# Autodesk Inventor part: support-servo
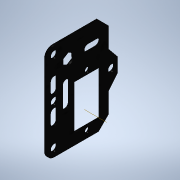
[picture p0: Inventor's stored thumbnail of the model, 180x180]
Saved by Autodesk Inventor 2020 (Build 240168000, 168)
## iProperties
Created: 2021-10
Part Number: support-servo
Material: Aluminium 6061
Document SubType Name: Tôle
Designer: bruno
Density: 4.82565 g/cm^3
Sheet Metal Rule: Par défaut_mm
Appearance: Noir
Mass: 5 g
Surface Area: 24.6113 cm^2
Volume: 1.03613 cm^3
Author: bruno
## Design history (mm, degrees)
sketch "Esquisse1"
  geometry: L1 (4, 0)-(44, 0); L2 (48, -4)-(48, -26); L3 (0, -26)-(0, -4); L4 (24, 0)-(24, -30.702); L5 (33.07, -2.25)-(28.57, -2.25); L6 (28.57, -5.75)-(33.07, -5.75); L7 (14.93, -2.25)-(19.43, -2.25); L8 (19.43, -5.75)-(14.93, -5.75); L9 (27.3, -26.952)-(5.3, -26.952); L10 (5.3, -26.952)-(5.3, -13.952); L11 (5.3, -13.952)-(27.3, -13.952); L12 (27.3, -13.952)-(27.3, -26.952); L13 (5, -30.982)-(0, -26); L14 (43, -30.982)-(48, -26); L15 (1.955, -20.452)-(29.582, -20.452); L16 (27.3, -26.952)-(43, -26.952); L17 (40.295, -20.701)-(40.3, -25.201); L18 (36.8, -20.832)-(36.8, -25.202); L19 (36.8, -26.952)-(36.8, -29.253); L20 (23.989, -34.202)-(23.989, -35.452); L21 (23.989, -35.452)-(27.489, -35.452); L22 (27.489, -35.452)-(32.95, -30.982); L23 (20.489, -35.452)-(15.027, -30.982); L24 (23.989, -35.452)-(20.489, -35.452); L25 (38.55, -25.202)-(38.55, -1.172); L26 (37.014, -8.556)-(39.898, -8.448); L27 (39.898, -8.448)-(41.435, -10.892); L28 (41.435, -10.892)-(40.086, -13.444); L29 (40.086, -13.444)-(37.202, -13.552); L30 (37.202, -13.552)-(35.665, -11.108); L31 (35.665, -11.108)-(37.014, -8.556); L32 (43, -30.982)-(32.95, -30.982); L33 (15.027, -30.982)-(5, -30.982); L34 (28.75, -11.75)-(24, -11.75); L35 (28.75, -8.25)-(24, -8.25); L36 (19.25, -8.25)-(24, -8.25); L37 (19.25, -11.75)-(24, -11.75); C1 r 1.75 at (44, -4); C2 r 1.75 at (4, -4); C3 r 1.75 at (24, -4); C4 r 1.25 at (29.3, -20.452); C5 r 1.25 at (3.3, -20.452); A1 r 4 centre (44, -4) between (48, -4) and (44, 0); A2 r 4 centre (4, -4) between (4, 0) and (0, -4); A3 r 1.75 centre (33.07, -4) between (33.07, -5.75) and (33.07, -2.25); A4 r 1.75 centre (28.57, -4) between (28.57, -2.25) and (28.57, -5.75); A5 r 1.75 centre (14.93, -4) between (14.93, -2.25) and (14.93, -5.75); A6 r 1.75 centre (19.43, -4) between (19.43, -5.75) and (19.43, -2.25); A7 r 1.75 centre (38.55, -25.202) between (36.8, -25.202) and (40.3, -25.201); A8 r 1.75 centre (38.545, -20.702) between (40.295, -20.701) and (36.8, -20.832); A9 r 1.75 centre (24.005, -32.452) between (23.989, -34.202) and (24, -30.702); A10 r 1.75 centre (28.75, -10) between (28.75, -11.75) and (28.75, -8.25); A11 r 1.75 centre (19.25, -10) between (19.25, -8.25) and (19.25, -11.75); 5 further points
  constraints: 74 end point, 22 point on circle, 16 centre point, 13 point on line, 11 symmetric about line, 11 tangent, 6 parallel, 5 perpendicular, 4 horizontal, 4 vertical, 2 coincident, 1 equal length, 1 equal radius, 1 midpoint, 16 other
  dimensions: "d0" = 48 distance of point (48, -31) point (0, -31); "d1" = 31 distance of point (48, 0) point (48, -31); "d2" = 4 radius of A1; "d3" = 3.5 diameter of C1; "d4" = 3.5 diameter of C2; "d5" = 3.5 diameter of C3; "d6" = 3.5 diameter of A3; "d7" = 3.5 diameter of A4; "d8" = 4.57015 distance from line of A4.centre L4; "d9" = 4.5 distance of A3.centre A4.centre; "d10" = 22 distance between parallel lines of L10 L12; "d11" = 13 distance of L9.end L10.end; "d12" = 5.3 distance between parallel lines of L3 L10; "d14" = 5 distance of L13.start point (0, -31); "d15" = 5 distance of L3.start point (0, -31) (= d14); "d16" = 5 distance of L14.start point (48, -31) (= d14); "d17" = 5 distance of L2.end point (48, -31) (= d16); "d18" = 2.5 diameter of C4; "d19" = 2.5 diameter of C5; "d20" = 26 distance of C4.centre C5.centre; "d21" = 2 distance from line of L12 C4.centre; "d22" = 3.5 diameter of A7; "d23" = 3.5 diameter of A8; "d24" = 4.5 distance of A8.centre L25.start; "d25" = 9.5 distance from line of L19.end L12; "d26" = 3.5 diameter of A9; "d27" = 3.5 distance of L20.end L21.end; "d28" = 3 distance from line of L21 A9.centre; "d29" = 11 distance from line of L1 point (38.55, -11); "d30" = 5 distance between parallel lines of L29 L26; "d31" = 3.5 diameter of A10; "d32" = 6 vertical distance of A10.centre A3.centre; "d33" = 4.75 distance from line of A10.centre L4; "d39" = 12 distance from line of L15 A9.centre; "d40" = 6.5 distance between parallel lines of L15 L11
extrude "Extrusion1" new body sketch "Esquisse1" distance "d34" = 1; taper "d35" = 0 deg
sketch "Esquisse2"
  geometry: L1 (-4, 24)-(-29.935, 24); L2 (-26.952, 27.3)-(-26.952, 5.3) reference; L3 (-20.35, 11.745)-(-20.304, 38); L4 (0, 44)-(0, 4) reference; C1 r 1.75 at (-4, 24) reference; C2 r 1.75 at (-32.452, 24.005) reference; C3 r 2.909 at (-20.452, 11.5); 1 further point
  constraints: 4 end point, 1 centre point, 1 perpendicular
  dimensions: "d38" = 12.10247 horizontal distance of L3.start C2.centre (derived); "d41" = 12.5 distance from line of L1 C3.centre; "d42" = 12 horizontal distance of C3.centre C2.centre
node "Axe de construction1"
node "Solide1"
other parameters: "Epaisseur" = 0.5 (derived), "FacteurX" = 4.4, "RayonPli" = 0.5 (= Epaisseur), "LargeurGrugeage" = 0.5 (= Epaisseur), "ProfondeurGrugeage" = 0.25 (= 0.5 x Epaisseur), "TailleGrugeage" = 2 (= 4 x Epaisseur), "JeuJointure" = 0.01, "RestesMinimum" = 1 (= 2 x Epaisseur), "Rayondetransition" = 0.5 (= RayonPli), "TailleRayonJacobi" = 0.5 (= RayonPli), "TailleJeu" = 0.5 (= Epaisseur), "d13" = 4.2
